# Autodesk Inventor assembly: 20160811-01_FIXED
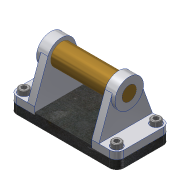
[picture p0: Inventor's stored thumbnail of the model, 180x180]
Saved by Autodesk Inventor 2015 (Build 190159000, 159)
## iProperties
Created: 2016-08
Part Number: 20160811-01_FIXED
Document SubType Name: Assembly
Designer: navara
Author: navara
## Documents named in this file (4)
- D:\20160811\20160811-01_FIXED.iam
- D:\20160811\20160811-02_FIXED.iam
- D:\20160811\20160811-01_FIXED.ipt
- D:\Dokumenty\CAD_DATA\Inventor_2015\Content Center Files\R2015\cs-CZ\ISO 4762(2)\ISO 4762 - M8 x 16ISO_FIXED.ipt
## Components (6 placed, 3 different names)
1. 20160811-02_FIXED:1 [sub-assembly]
2. 20160811-01_FIXED:1
3. ISO 4762 - M8 x 16ISO_FIXED:1
4. ISO 4762 - M8 x 16ISO_FIXED:2
5. ISO 4762 - M8 x 16ISO_FIXED:3
6. ISO 4762 - M8 x 16ISO_FIXED:4
